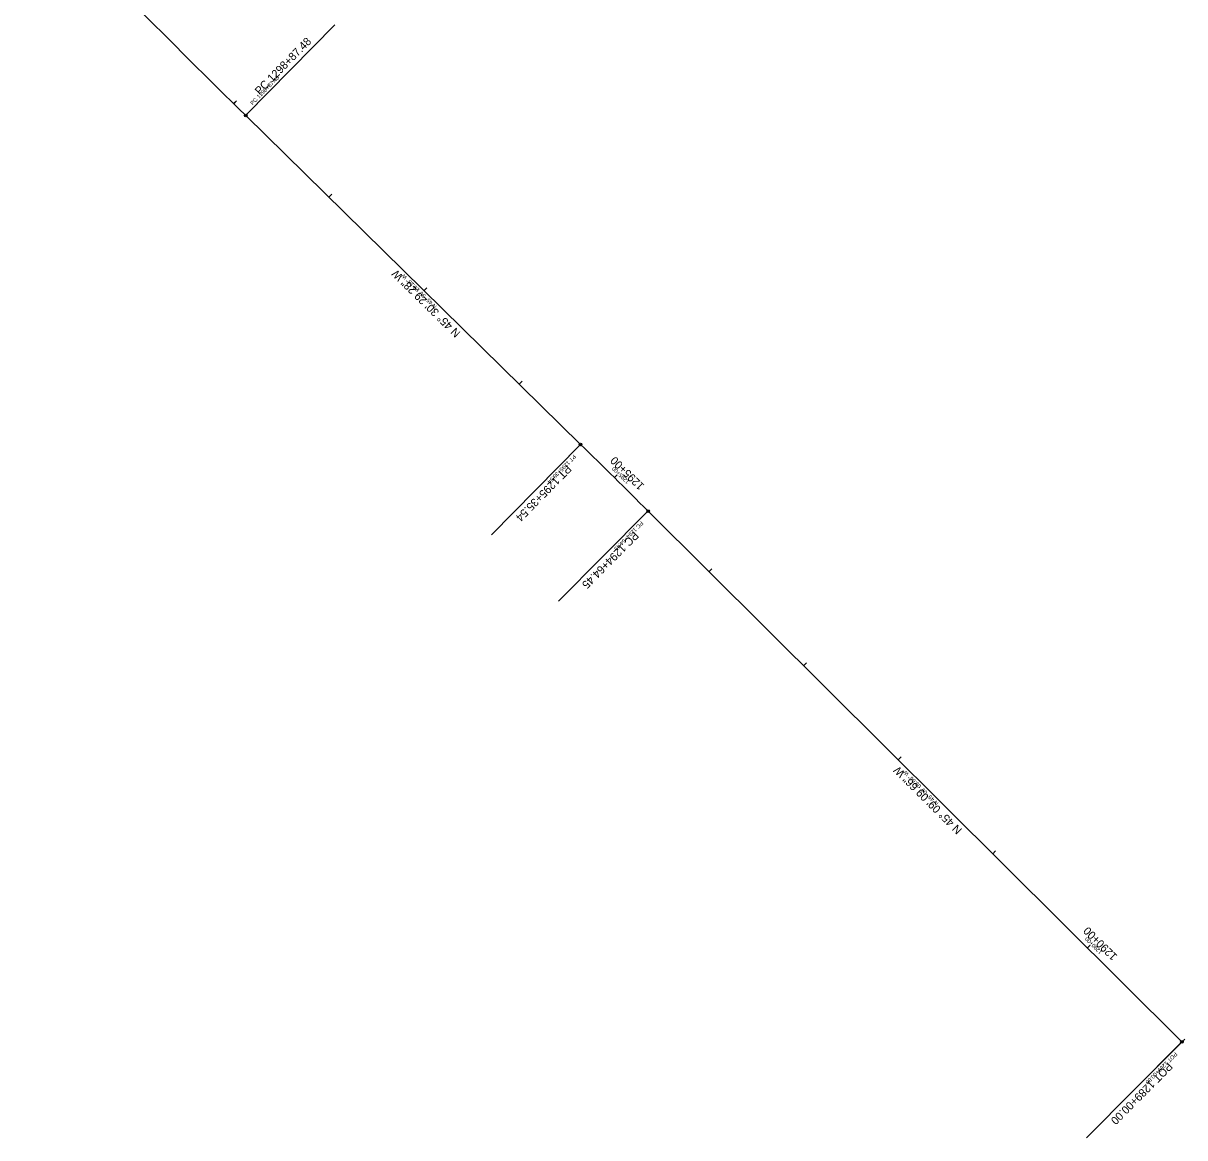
# Model space of a CAD drawing. Extents: x 2252205 to 2259955, y 13788514 to 13798103.
# Drawn here: x 2259084 to 2259955, y 13788514 to 13789350 of the extents above; entities that cross this region are included whole.
import ezdxf

# ---------------------------------------------------------------- set-up
doc = ezdxf.new("R2010")
doc.units = 0
for name, color, linetype in [('GEOM_CENTERLINE_ALIGN', 7, 'Continuous'), ('GEOM_CENTERLINE_PCPT_100', 7, 'Continuous'), ('GEOM_CENTERLINE_PCPT_50', 7, 'Continuous'), ('GEOM_CENTERLINE_STA_100', 7, 'Continuous'), ('GEOM_CENTERLINE_STA_50', 7, 'Continuous')]:
    doc.layers.add(name, color=color, linetype=linetype)

msp = doc.modelspace()

# ---------------------------------------------------------------- linework, layer by layer
at = {"layer": 'GEOM_CENTERLINE_ALIGN'}
for p, q in [((2259502.22, 13789034.01), (2259251.17, 13789280.65)), ((2259952.97, 13788585.97), (2259552.78, 13788984.04))]:
    msp.add_line(p, q, dxfattribs=at)
for centre, start, end in [((2267281.84, 13797455.04), 224.327385, 225.508134), ((2251471.55, 13780859.62), 45.152685, 45.508134)]:
    msp.add_arc(centre, 11459.16, start, end, dxfattribs=at)
at = {"layer": 'GEOM_CENTERLINE_PCPT_100'}
for p, q in [((2259251.87, 13789281.37), (2259317.89, 13789348.57)), ((2259501.52, 13789033.3), (2259435.53, 13788966.13)), ((2259552.07, 13788983.33), (2259485.63, 13788916.53)), ((2259952.26, 13788585.26), (2259881.49, 13788514.11))]:
    msp.add_line(p, q, dxfattribs=at)
at = {"layer": 'GEOM_CENTERLINE_PCPT_50'}
for p, q in [((2259251.52, 13789281.01), (2259284.53, 13789314.61)), ((2259501.87, 13789033.66), (2259468.88, 13789000.07)), ((2259552.43, 13788983.68), (2259519.21, 13788950.28)), ((2259952.62, 13788585.62), (2259917.23, 13788550.04))]:
    msp.add_line(p, q, dxfattribs=at)
at = {"layer": 'GEOM_CENTERLINE_STA_100'}
for p, q in [((2259242.24, 13789289.43), (2259244.35, 13789291.57)), ((2259313.57, 13789219.35), (2259315.67, 13789221.49)), ((2259384.91, 13789149.26), (2259387.01, 13789151.4)), ((2259456.24, 13789079.18), (2259458.34, 13789081.32)), ((2259527.54, 13789009.06), (2259529.65, 13789011.2)), ((2259598.48, 13788938.58), (2259600.59, 13788940.71)), ((2259669.37, 13788868.06), (2259671.49, 13788870.19)), ((2259740.27, 13788797.54), (2259742.39, 13788799.66)), ((2259811.17, 13788727.01), (2259813.29, 13788729.14)), ((2259882.07, 13788656.49), (2259884.19, 13788658.62)), ((2259952.97, 13788585.97), (2259955.09, 13788588.1))]:
    msp.add_line(p, q, dxfattribs=at)
for centre in [(2259251.17, 13789280.65), (2259502.22, 13789034.01), (2259552.78, 13788984.04), (2259952.97, 13788585.97)]:
    msp.add_circle(centre, 1, dxfattribs=at)
at = {"layer": 'GEOM_CENTERLINE_STA_50'}
for p, q in [((2259242.24, 13789289.43), (2259243.29, 13789290.5)), ((2259313.57, 13789219.35), (2259314.62, 13789220.42)), ((2259384.91, 13789149.26), (2259385.96, 13789150.33)), ((2259456.24, 13789079.18), (2259457.29, 13789080.25)), ((2259527.54, 13789009.06), (2259528.59, 13789010.13)), ((2259598.48, 13788938.58), (2259599.53, 13788939.64)), ((2259669.37, 13788868.06), (2259670.43, 13788869.12)), ((2259740.27, 13788797.54), (2259741.33, 13788798.6)), ((2259811.17, 13788727.01), (2259812.23, 13788728.08)), ((2259882.07, 13788656.49), (2259883.13, 13788657.56)), ((2259952.97, 13788585.97), (2259954.03, 13788587.03))]:
    msp.add_line(p, q, dxfattribs=at)
for centre in [(2259251.17, 13789280.65), (2259502.22, 13789034.01), (2259552.78, 13788984.04), (2259952.97, 13788585.97)]:
    msp.add_circle(centre, 0.5, dxfattribs=at)

# ---------------------------------------------------------------- texts
at = {"layer": 'GEOM_CENTERLINE_PCPT_100'}
for s, rotation, p in [('PC 1298+87.48', 45.50813, (2259261.64, 13789295.6)), ('PT 1295+35.54', 225.50813, (2259491.75, 13789019.07)), ('PC 1294+64.45', 225.15268, (2259542.21, 13788969.16)), ('POT 1289+00.00', 225.15268, (2259942.4, 13788571.09))]:
    msp.add_text(s, height=6, rotation=rotation, dxfattribs=at).set_placement(p)
at = {"layer": 'GEOM_CENTERLINE_PCPT_50'}
for s, rotation, p in [('PC 1298+87.48', 45.50813, (2259256.4, 13789288.12)), ('PT 1295+35.54', 225.50813, (2259496.98, 13789026.54)), ('PC 1294+64.45', 225.15268, (2259547.49, 13788976.6)), ('POT 1289+00.00', 225.15268, (2259947.69, 13788578.53))]:
    msp.add_text(s, height=3, rotation=rotation, dxfattribs=at).set_placement(p)
at = {"layer": 'GEOM_CENTERLINE_STA_100'}
for s, rotation, p in [('N 45%%d 30\' 29.28" W', 135.50813, (2259412.58, 13789117.88)), ('1295+00', 135.33041, (2259550.44, 13789003.3)), ('N 45%%d 09\' 09.66" W', 135.15268, (2259788.51, 13788745.33)), ('1290+00', 135.15268, (2259904.96, 13788650.65))]:
    msp.add_text(s, height=6, rotation=rotation, dxfattribs=at).set_placement(p)
at = {"layer": 'GEOM_CENTERLINE_STA_50'}
for s, rotation, p in [('N 45%%d 30\' 29.28" W', 135.50813, (2259394.63, 13789137.6)), ('1295+00', 135.33041, (2259538.99, 13789006.18)), ('N 45%%d 09\' 09.66" W', 135.15268, (2259770.69, 13788765.16)), ('1290+00', 135.15268, (2259893.51, 13788653.57))]:
    msp.add_text(s, height=3, rotation=rotation, dxfattribs=at).set_placement(p)

doc.saveas('drawing.dxf')
